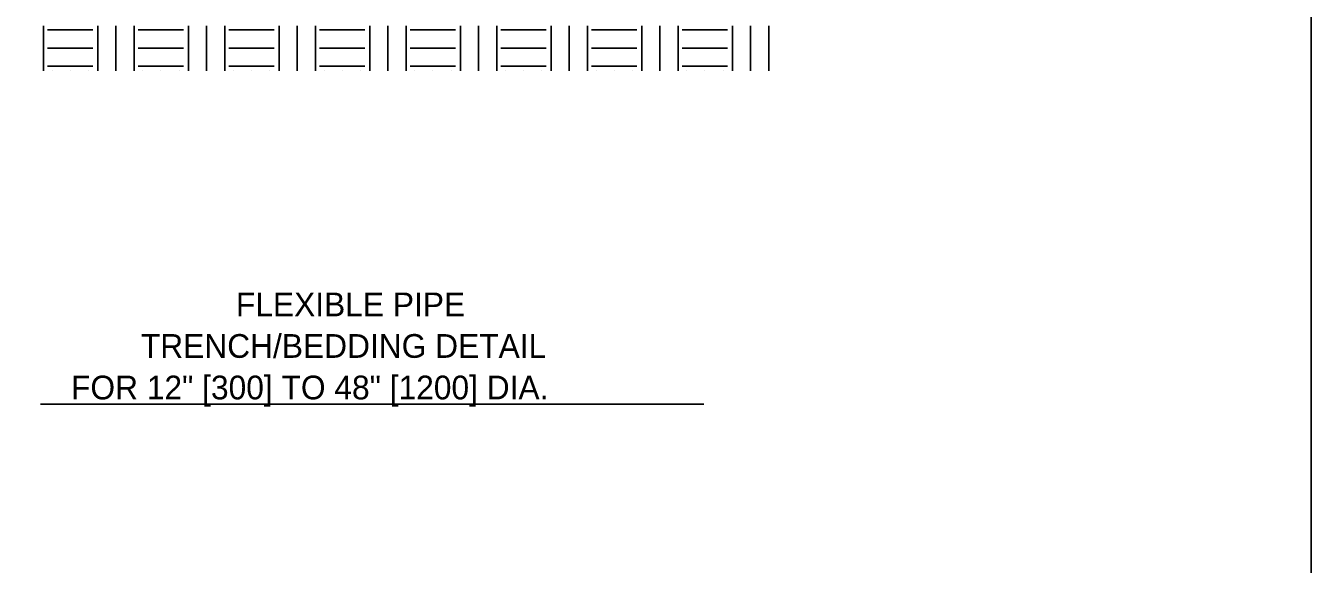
# Model space of a CAD drawing. Extents: x 49991.4 to 50061.4, y 49960.6 to 50011.4.
# Drawn here: x 50012.414 to 50016.75, y 49993.734 to 49995.549 of the extents above; entities that cross this region are included whole.
import ezdxf

# ---------------------------------------------------------------- set-up
doc = ezdxf.new("R2010")
doc.units = 0
doc.layers.add('Level 1', color=7, linetype='Continuous')
doc.layers.add('Level 2', color=7, linetype='Continuous')

msp = doc.modelspace()

# ---------------------------------------------------------------- linework, layer by layer
at = {"layer": 'Level 1'}
for p, q in [((50012.4741, 49995.5492), (50012.4741, 49995.3967)), ((50012.4882, 49995.535), (50012.6411, 49995.535)), ((50012.6575, 49995.5492), (50012.6575, 49995.3967)), ((50012.7187, 49995.5492), (50012.7187, 49995.3967)), ((50012.7798, 49995.5492), (50012.7798, 49995.3967)), ((50012.794, 49995.535), (50012.9469, 49995.535)), ((50012.9633, 49995.5492), (50012.9633, 49995.3967)), ((50013.0244, 49995.5492), (50013.0244, 49995.3967)), ((50013.0856, 49995.5492), (50013.0856, 49995.3967)), ((50013.0997, 49995.535), (50013.2526, 49995.535)), ((50013.269, 49995.5492), (50013.269, 49995.3967)), ((50013.3302, 49995.5492), (50013.3302, 49995.3967)), ((50013.3914, 49995.5492), (50013.3914, 49995.3967)), ((50013.4055, 49995.535), (50013.5584, 49995.535)), ((50013.5748, 49995.5492), (50013.5748, 49995.3967)), ((50013.636, 49995.5492), (50013.636, 49995.3967)), ((50013.6971, 49995.5492), (50013.6971, 49995.3967)), ((50013.7113, 49995.535), (50013.8642, 49995.535)), ((50013.8806, 49995.5492), (50013.8806, 49995.3967)), ((50013.9417, 49995.5492), (50013.9417, 49995.3967)), ((50014.0029, 49995.5492), (50014.0029, 49995.3967)), ((50014.017, 49995.535), (50014.1699, 49995.535)), ((50014.1863, 49995.5492), (50014.1863, 49995.3967)), ((50014.2475, 49995.5492), (50014.2475, 49995.3967)), ((50014.3087, 49995.5492), (50014.3087, 49995.3967)), ((50014.3228, 49995.535), (50014.4757, 49995.535)), ((50014.4921, 49995.5492), (50014.4921, 49995.3967)), ((50014.5533, 49995.5492), (50014.5533, 49995.3967)), ((50014.6144, 49995.5492), (50014.6144, 49995.3967)), ((50014.6286, 49995.535), (50014.7815, 49995.535)), ((50014.7979, 49995.5492), (50014.7979, 49995.3967)), ((50014.859, 49995.5492), (50014.859, 49995.3967)), ((50014.9202, 49995.5492), (50014.9202, 49995.3967)), ((50012.4882, 49995.4738), (50012.6411, 49995.4738)), ((50012.794, 49995.4738), (50012.9469, 49995.4738)), ((50013.0997, 49995.4738), (50013.2526, 49995.4738)), ((50013.4055, 49995.4738), (50013.5584, 49995.4738)), ((50013.7113, 49995.4738), (50013.8642, 49995.4738)), ((50014.017, 49995.4738), (50014.1699, 49995.4738)), ((50014.3228, 49995.4738), (50014.4757, 49995.4738)), ((50014.6286, 49995.4738), (50014.7815, 49995.4738)), ((50012.4882, 49995.4127), (50012.6411, 49995.4127)), ((50012.5035, 49995.3974), (50012.5035, 49995.3967)), ((50012.5647, 49995.3974), (50012.5647, 49995.3967)), ((50012.6258, 49995.3974), (50012.6258, 49995.3967)), ((50012.794, 49995.4127), (50012.9469, 49995.4127)), ((50012.8093, 49995.3974), (50012.8093, 49995.3967)), ((50012.8704, 49995.3974), (50012.8704, 49995.3967)), ((50012.9316, 49995.3974), (50012.9316, 49995.3967)), ((50013.0997, 49995.4127), (50013.2526, 49995.4127)), ((50013.115, 49995.3974), (50013.115, 49995.3967)), ((50013.1762, 49995.3974), (50013.1762, 49995.3967)), ((50013.2373, 49995.3974), (50013.2373, 49995.3967)), ((50013.4055, 49995.4127), (50013.5584, 49995.4127)), ((50013.4208, 49995.3974), (50013.4208, 49995.3967)), ((50013.482, 49995.3974), (50013.482, 49995.3967)), ((50013.5431, 49995.3974), (50013.5431, 49995.3967)), ((50013.7113, 49995.4127), (50013.8642, 49995.4127)), ((50013.7266, 49995.3974), (50013.7266, 49995.3967)), ((50013.7877, 49995.3974), (50013.7877, 49995.3967)), ((50013.8489, 49995.3974), (50013.8489, 49995.3967)), ((50014.017, 49995.4127), (50014.1699, 49995.4127)), ((50014.0323, 49995.3974), (50014.0323, 49995.3967)), ((50014.0935, 49995.3974), (50014.0935, 49995.3967)), ((50014.1546, 49995.3974), (50014.1546, 49995.3967)), ((50014.3228, 49995.4127), (50014.4757, 49995.4127)), ((50014.3381, 49995.3974), (50014.3381, 49995.3967)), ((50014.3993, 49995.3974), (50014.3993, 49995.3967)), ((50014.4604, 49995.3974), (50014.4604, 49995.3967)), ((50014.6286, 49995.4127), (50014.7815, 49995.4127)), ((50014.6439, 49995.3974), (50014.6439, 49995.3967)), ((50014.705, 49995.3974), (50014.705, 49995.3967)), ((50014.7662, 49995.3974), (50014.7662, 49995.3967))]:
    msp.add_line(p, q, dxfattribs=at)
msp.add_lwpolyline([(49999.3835, 49998.9992), (50016.7501, 49998.9992), (50016.7501, 49987.7988), (49999.3835, 49987.7988)], close=True, dxfattribs=at)
at = {"layer": 'Level 2'}
msp.add_line((50012.464, 49994.2737), (50014.7013, 49994.2737), dxfattribs=at)

# ---------------------------------------------------------------- texts
for s, p in [('FLEXIBLE PIPE', (50013.1233, 49994.5697)), ('TRENCH/BEDDING DETAIL', (50012.8027, 49994.4297)), ('FOR 12" [300] TO 48" [1200] DIA.', (50012.5672, 49994.2897))]:
    msp.add_text(s, height=0.08, dxfattribs=at).set_placement(p)

doc.saveas('drawing.dxf')
